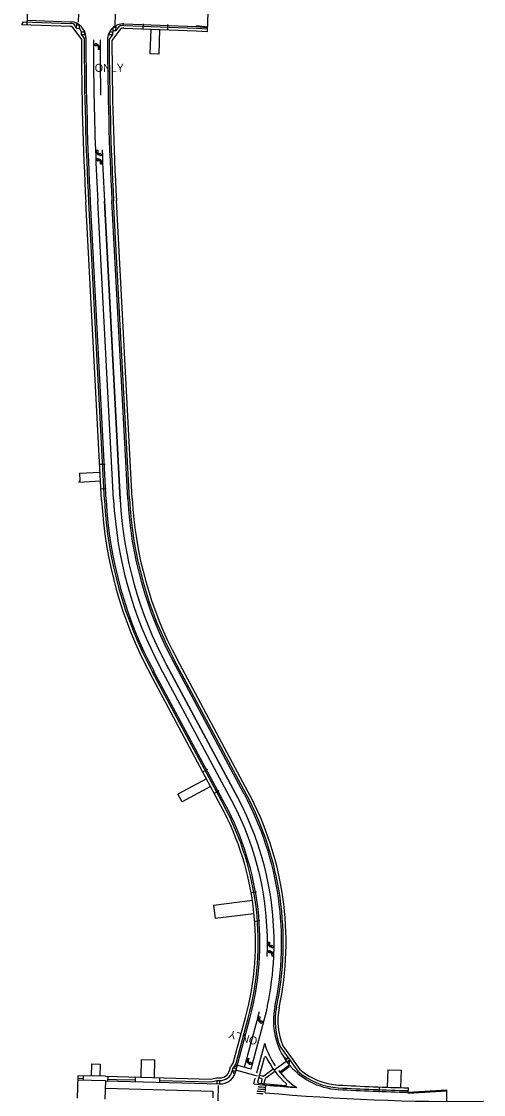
# Model space of a CAD drawing. Extents: x 979036 to 996074, y 1836928 to 1845163.
# Drawn here: x 992337 to 993169, y 1840671 to 1842602 of the extents above; entities that cross this region are included whole.
import ezdxf

# ---------------------------------------------------------------- set-up
doc = ezdxf.new("R2010")
doc.units = 0
for name, color, linetype in [('R_Proposed Road', 7, 'Continuous'), ('STRIPE_White Crosswalk', 7, 'Continuous'), ('STRIPE_White Stopbar', 7, 'Continuous'), ('STRIPE_White Turn Arrow', 7, 'Continuous'), ('STRIPE_White_6in', 7, 'Continuous'), ('STRIPE_White_ONLY', 7, 'Continuous'), ('STRIPE_White_Yield Tri', 7, 'Continuous'), ('STRIPE_Yellow Dbl 6in', 7, 'Continuous'), ('STRIPE_Yellow_10_30 SKIP', 7, 'Continuous'), ('STRIPE_Yellow_45_Diag_8in', 7, 'Continuous')]:
    doc.layers.add(name, color=color, linetype=linetype)

msp = doc.modelspace()

# ---------------------------------------------------------------- linework, layer by layer
at = {"layer": 'R_Proposed Road'}
for p, q in [((992348.7, 1842643.5), (992347, 1842596.5)), ((992671.8, 1842584.2), (992673.6, 1842635.6)), ((992340.2, 1842601.8), (992337.3, 1842596.9)), ((992337.3, 1842596.9), (992425.4, 1842593.7)), ((992340.2, 1842601.8), (992425.6, 1842598.7)), ((992347.3, 1842604.5), (992425.7, 1842601.7)), ((992427.9, 1842593.4), (992445.2, 1842569.9)), ((992430.8, 1842597.9), (992436.5, 1842590.2)), ((992436.5, 1842590.2), (992436.8, 1842599)), ((992436.5, 1842590.2), (992441.5, 1842590)), ((992436.7, 1842596.2), (992441.7, 1842596)), ((992441.5, 1842590), (992441.7, 1842596)), ((992441.5, 1842590), (992445.4, 1842583.1)), ((992502.1, 1842585.5), (992502.3, 1842591.5)), ((992507.3, 1842591.3), (992502.3, 1842591.5)), ((992507.1, 1842585.3), (992507.4, 1842594.9)), ((992507.1, 1842585.3), (992514, 1842594.3)), ((992521.4, 1842590.2), (992651.8, 1842585.4)), ((992521.6, 1842595.2), (992652, 1842590.4)), ((992521.7, 1842598.1), (992652.1, 1842593.4)), ((992556.2, 1842598.4), (992555.8, 1842588.9)), ((992600.2, 1842596.8), (992599.8, 1842587.3)), ((992652, 1842590.4), (992671.9, 1842589.2)), ((992652.1, 1842594.9), (992672.1, 1842593)), ((992652.1, 1842593.4), (992672, 1842591.5)), ((992445.4, 1842578.1), (992445.4, 1842583.1)), ((992451.4, 1842583.1), (992445.4, 1842583.1)), ((992445.4, 1842578.1), (992450.2, 1842571.6)), ((992452.7, 1842578.1), (992445.4, 1842578.1)), ((992451.4, 1842578.1), (992451.4, 1842583.1)), ((992501.5, 1842578.1), (992493.4, 1842578.1)), ((992495.2, 1842569.8), (992501.5, 1842578.1)), ((992501.5, 1842583.1), (992495.5, 1842583.1)), ((992495.5, 1842578.1), (992495.5, 1842583.1)), ((992500.2, 1842568.1), (992516.9, 1842589.8)), ((992502.1, 1842585.5), (992501.5, 1842583.1)), ((992501.5, 1842578.1), (992501.5, 1842583.1)), ((992507.1, 1842585.3), (992502.1, 1842585.5)), ((992569.8, 1842588.4), (992568.2, 1842544.1)), ((992585.8, 1842587.8), (992584.2, 1842543.6)), ((992651.8, 1842585.4), (992671.8, 1842584.2)), ((992584.2, 1842543.6), (992568.2, 1842544.1)), ((992481.5, 1841740.8), (992453.2, 1842277.1)), ((992486.5, 1841741), (992458.2, 1842277.4)), ((992489.5, 1841741.2), (992461.2, 1842277.5)), ((992528.4, 1841743.3), (992500.1, 1842279.6)), ((992531.4, 1841743.4), (992503.1, 1842279.7)), ((992536.4, 1841743.7), (992508.1, 1842280)), ((992478.1, 1841805.4), (992487.6, 1841805.9)), ((992441.4, 1841789.5), (992478.8, 1841791.5)), ((992440.6, 1841773.4), (992479.7, 1841775.5)), ((992480.4, 1841761.5), (992489.9, 1841762)), ((992738.3, 1841211.7), (992610.1, 1841450.8)), ((992740.9, 1841213.2), (992612.8, 1841452.3)), ((992745.3, 1841215.5), (992617.2, 1841454.6)), ((992703.9, 1841193.3), (992575.7, 1841432.4)), ((992696.9, 1841189.5), (992568.7, 1841428.6)), ((992701.3, 1841191.9), (992573.1, 1841431)), ((992670.1, 1841239.5), (992618.7, 1841212)), ((992671.8, 1841256.3), (992663.5, 1841251.8)), ((992677.6, 1841225.4), (992626.3, 1841197.9)), ((992626.3, 1841197.9), (992618.7, 1841212)), ((992692.6, 1841217.5), (992684.3, 1841213)), ((992760, 1841035.2), (992750.6, 1841034.1)), ((992752.8, 1841020.3), (992682.9, 1841011.6)), ((992682.9, 1841011.6), (992685.9, 1840987.8)), ((992755.7, 1840996.4), (992685.9, 1840987.8)), ((992766.4, 1840983.6), (992757, 1840982.5)), ((992718.9, 1840729.8), (992740.5, 1840810)), ((992722.3, 1840711.4), (992748.3, 1840808)), ((992723.6, 1840727.8), (992745.4, 1840808.7)), ((992803.3, 1840756.4), (992834.7, 1840712.9)), ((992807.7, 1840758.9), (992838.4, 1840716.3)), ((992762.6, 1840693.9), (992774.4, 1840737.7)), ((992809.5, 1840738), (992817.5, 1840736.7)), ((992817.5, 1840736.7), (992812.7, 1840733.2)), ((992821.6, 1840739.7), (992824.5, 1840735.6)), ((992463.1, 1840726.5), (992462.5, 1840704.3)), ((992463.1, 1840726.5), (992479.1, 1840725.9)), ((992479.1, 1840725.9), (992478.5, 1840704.1)), ((992552.5, 1840702.2), (992553.4, 1840734.3)), ((992553.4, 1840734.3), (992577.4, 1840733.6)), ((992576.5, 1840701.5), (992577.4, 1840733.6)), ((992711.6, 1840714.2), (992713.4, 1840720.9)), ((992718.9, 1840729.8), (992713.4, 1840720.9)), ((992716.5, 1840712.9), (992718.1, 1840718.9)), ((992723.6, 1840727.8), (992718.1, 1840718.9)), ((992725.4, 1840723.1), (992718.1, 1840718.9)), ((992723.9, 1840717.3), (992718.1, 1840718.9)), ((992773.3, 1840704.8), (992790.4, 1840717.1)), ((992820.4, 1840732.7), (992815.6, 1840729.2)), ((992819.2, 1840724.6), (992820.4, 1840732.7)), ((992438.5, 1840704.8), (992437.4, 1840664.3)), ((992448.4, 1840699.6), (992438.4, 1840699.8)), ((992488.5, 1840703.9), (992438.5, 1840704.8)), ((992448.5, 1840704.6), (992448.3, 1840696.6)), ((992488.5, 1840703.9), (992678.2, 1840698.7)), ((992492.5, 1840703.8), (992492.3, 1840695.8)), ((992492.4, 1840698.7), (992508.4, 1840698.4)), ((992508.4, 1840698.4), (992542.4, 1840697.4)), ((992542.3, 1840693.1), (992542.5, 1840702.4)), ((992586.2, 1840691.9), (992586.5, 1840701.2)), ((992678.2, 1840698.7), (992688.3, 1840701.4)), ((992688.3, 1840701.4), (992694.3, 1840701.3)), ((992722.6, 1840712.5), (992716.8, 1840714.1)), ((992720.8, 1840707.2), (992716.8, 1840714.1)), ((992768.9, 1840700), (992764.6, 1840701.2)), ((992765.9, 1840706), (992771.6, 1840704.5)), ((992768.6, 1840691), (992770.3, 1840697.6)), ((992773.6, 1840690.6), (992776.2, 1840700.1)), ((992776.9, 1840701.2), (992793.3, 1840713)), ((992996.5, 1840715.8), (992995.6, 1840684.3)), ((992996.5, 1840715.8), (993020.5, 1840715.1)), ((993020.5, 1840715.1), (993019.6, 1840683.5)), ((992488.3, 1840695.9), (992438.3, 1840696.8)), ((992488.3, 1840695.9), (992487.4, 1840662.9)), ((992488.3, 1840695.9), (992694, 1840690.3)), ((992586.4, 1840696.2), (992678.8, 1840693.7)), ((992678.8, 1840693.7), (992688.9, 1840696.4)), ((992688.9, 1840696.4), (992694.1, 1840696.3)), ((992764.4, 1840691.4), (992785.5, 1840689.5)), ((992981.2, 1840675.2), (992981.6, 1840684.7)), ((993033.1, 1840675.2), (993102.9, 1840679.3)), ((993033.3, 1840673.7), (993033.6, 1840683.2)), ((993102.7, 1840635.2), (993102.9, 1840679.3)), ((993033.2, 1840673.7), (993102.9, 1840677.8))]:
    msp.add_line(p, q, dxfattribs=at)
for points in [[(992441.4, 1841789.5), (992442, 1841776.5), (992440.6, 1841773.4)], [(992688.9, 1840696.4), (992688.7, 1840690.4)], [(992693.9, 1840696.3), (992693.7, 1840690.3)]]:
    msp.add_lwpolyline(points, dxfattribs=at)
for centre, radius, start, end in [((992424.7, 1842573.2), 20.5, 80.8565, 87.9024), ((992424.7, 1842573.2), 25.5, 76.0433, 87.9024), ((992424.7, 1842573.2), 28.5, 0.0744, 87.9024), ((992520.7, 1842569.7), 28.5, 87.9024, 180.1112), ((992520.7, 1842569.7), 25.5, 87.9024, 105.1165), ((992520.7, 1842569.7), 20.5, 87.9024, 100.6335), ((998202.2, 1842580.7), 5752.1, 180.09065, 183.02281), ((998202.2, 1842580.7), 5749.1, 180.07443, 183.02281), ((998202.2, 1842580.7), 5757.1, 180.10692, 183.02281), ((998202.2, 1842580.7), 5710.1, 180.1112, 183.0228), ((992520.7, 1842569.7), 25.5, 179.6047, 180.1112), ((998202.2, 1842580.7), 5707.1, 180.1112, 183.0228), ((998202.2, 1842580.7), 5707.1, 180.1112, 183.0228), ((998202.2, 1842580.7), 5702.1, 180.1261, 183.0228), ((998202.2, 1842580.7), 5702.1, 180.1261, 183.0228), ((993224.2, 1841780), 743.7, 183.0228, 208.1934), ((993224.2, 1841780), 738.7, 183.0228, 208.1934), ((993224.2, 1841780), 735.7, 183.0228, 208.1934), ((993224.2, 1841780), 696.7, 183.0228, 208.1934), ((993224.2, 1841780), 693.7, 183.0228, 208.1934), ((993224.2, 1841780), 688.7, 183.0228, 208.1934), ((992240.2, 1840944.7), 565.2, 348.1671, 28.1934), ((992240.2, 1840944.7), 568.2, 348.1671, 28.1934), ((992240.2, 1840944.7), 573.2, 348.1671, 28.1934), ((992240.2, 1840944.7), 518.2, 344.9354, 28.1934), ((992240.2, 1840944.7), 523.2, 344.9354, 28.1934), ((992240.2, 1840944.7), 526.2, 344.9354, 28.1934), ((992914.2, 1840803.5), 123.5, 168.1671, 266.7749), ((992914.2, 1840803.5), 120.5, 168.1671, 202.9851), ((992914.2, 1840803.5), 115.5, 168.1671, 202.7083), ((992776.3, 1840737.2), 2, 25.6869, 164.9354), ((992914.2, 1840803.5), 151, 205.6869, 228.317), ((992694.7, 1840718.8), 28.5, 268.4354, 344.9354), ((992694.7, 1840718.8), 22.5, 268.4354, 344.9354), ((992694.7, 1840718.8), 17.5, 268.4354, 344.9354), ((992768.4, 1840698.1), 2, 344.9354, 74.9354), ((992772.2, 1840706.4), 2, 254.9354, 305.851), ((992778.1, 1840699.6), 2, 125.851, 164.9354), ((992914.2, 1840803.5), 120.5, 228.717, 266.7749), ((992914.2, 1840803.5), 115.5, 228.9937, 266.7749), ((992764.5, 1840693.4), 2, 164.9354, 264.9354), ((993121.3, 1844478.4), 3803.7, 264.9354, 265.3407), ((992812.5, 1840689.2), 2, 265.3407, 48.317), ((993121.3, 1844478.4), 3804.2, 266.7749, 268.6736), ((993121.3, 1844478.4), 3801.2, 266.7749, 268.676), ((993121.3, 1844478.4), 3796.2, 266.7749, 268.676)]:
    msp.add_arc(centre, radius, start, end, dxfattribs=at)
at = {"layer": 'STRIPE_White Crosswalk'}
for p, q in [((992440.5, 1842632.3), (992439.4, 1842601.3)), ((992506.3, 1842632.1), (992505, 1842596.3)), ((992813, 1840730.1), (992791.8, 1840715)), ((992762.3, 1840704.4), (992724.7, 1840714.5)), ((992691.2, 1840687.3), (992690.4, 1840659.5))]:
    msp.add_line(p, q, dxfattribs=at)
for points in [[(992773.4, 1840680.7), (992773.3, 1840679.7), (992763.3, 1840680.6), (992763.4, 1840681.6)], [(992774.4, 1840684.5), (992774.3, 1840683.6), (992764.4, 1840684.4), (992764.5, 1840685.4)], [(992775.5, 1840688.4), (992775.4, 1840687.4), (992765.4, 1840688.3), (992765.5, 1840689.3)], [(992771.3, 1840673), (992771.2, 1840672), (992761.2, 1840672.8), (992761.3, 1840673.8)], [(992772.3, 1840676.8), (992772.2, 1840675.8), (992762.3, 1840676.7), (992762.4, 1840677.7)]]:
    msp.add_lwpolyline(points, close=True, dxfattribs=at)
at = {"layer": 'STRIPE_White Stopbar'}
for p, q in [((992750.2, 1840717), (992727, 1840723.2)), ((992776, 1840674.3), (992777.2, 1840688.2)), ((992681.9, 1840677.1), (992681.5, 1840665.1))]:
    msp.add_line(p, q, dxfattribs=at)
at = {"layer": 'STRIPE_White Turn Arrow'}
for points in [[(992471.9, 1842558), (992468.3, 1842560.3), (992471.4, 1842563.3), (992471.6, 1842561.6), (992472.3, 1842561.6), (992472.8, 1842561.6), (992473.6, 1842561.4), (992474.6, 1842561), (992475.3, 1842560.6), (992475.9, 1842560.1), (992476.6, 1842559.4), (992477, 1842558.8), (992477.4, 1842558), (992477.7, 1842557.1), (992477.8, 1842556.1), (992477.8, 1842552.2), (992475.8, 1842552.2), (992475.8, 1842555.8), (992475.8, 1842556.5), (992475.5, 1842557.2), (992475.2, 1842558), (992474.6, 1842558.7), (992474.3, 1842558.9), (992473.7, 1842559.3), (992472.9, 1842559.5), (992472.2, 1842559.6), (992471.8, 1842559.6)], [(992478.5, 1842365.3), (992482.3, 1842363.1), (992479.3, 1842360), (992479, 1842361.7), (992478.4, 1842361.6), (992477.8, 1842361.6), (992477, 1842361.8), (992476, 1842362.1), (992475.3, 1842362.5), (992474.6, 1842363), (992473.9, 1842363.6), (992473.5, 1842364.3), (992473, 1842365), (992472.7, 1842365.9), (992472.5, 1842366.9), (992472.4, 1842370.8), (992474.4, 1842370.9), (992474.6, 1842367.3), (992474.6, 1842366.6), (992474.9, 1842365.9), (992475.3, 1842365.1), (992475.9, 1842364.5), (992476.2, 1842364.3), (992476.8, 1842363.9), (992477.6, 1842363.7), (992478.3, 1842363.6), (992478.7, 1842363.6)], [(992475.4, 1842350.9), (992471.5, 1842353), (992474.6, 1842356.2), (992474.8, 1842354.5), (992475.5, 1842354.6), (992476.1, 1842354.6), (992476.9, 1842354.4), (992477.8, 1842354.1), (992478.6, 1842353.7), (992479.2, 1842353.2), (992479.9, 1842352.6), (992480.4, 1842352), (992480.8, 1842351.2), (992481.1, 1842350.3), (992481.3, 1842349.3), (992481.5, 1842345.4), (992479.5, 1842345.4), (992479.3, 1842349), (992479.2, 1842349.6), (992479, 1842350.4), (992478.6, 1842351.1), (992478, 1842351.7), (992477.7, 1842351.9), (992477, 1842352.3), (992476.2, 1842352.5), (992475.5, 1842352.6), (992475.1, 1842352.6)], [(992784.2, 1840925.6), (992780.4, 1840927.8), (992783.5, 1840930.9), (992783.7, 1840929.3), (992784.4, 1840929.3), (992784.9, 1840929.3), (992785.7, 1840929.1), (992786.7, 1840928.8), (992787.4, 1840928.4), (992788.1, 1840927.9), (992788.8, 1840927.2), (992789.2, 1840926.6), (992789.6, 1840925.8), (992789.9, 1840924.9), (992790.1, 1840923.9), (992790.2, 1840920), (992788.2, 1840920), (992788.1, 1840923.6), (992788, 1840924.3), (992787.8, 1840925), (992787.4, 1840925.8), (992786.8, 1840926.4), (992786.5, 1840926.6), (992785.8, 1840927), (992785.1, 1840927.2), (992784.3, 1840927.3), (992783.9, 1840927.3)], [(992787.5, 1840940), (992791.3, 1840937.8), (992788.2, 1840934.7), (992788, 1840936.3), (992787.3, 1840936.3), (992786.8, 1840936.3), (992786, 1840936.5), (992785, 1840936.8), (992784.3, 1840937.2), (992783.6, 1840937.7), (992782.9, 1840938.3), (992782.5, 1840939), (992782.1, 1840939.7), (992781.8, 1840940.6), (992781.6, 1840941.6), (992781.5, 1840945.5), (992783.5, 1840945.6), (992783.6, 1840942), (992783.7, 1840941.3), (992783.9, 1840940.6), (992784.3, 1840939.8), (992784.9, 1840939.2), (992785.2, 1840939), (992785.9, 1840938.6), (992786.6, 1840938.4), (992787.4, 1840938.3), (992787.8, 1840938.3)], [(992769, 1840804.4), (992772, 1840801.3), (992768.2, 1840799.1), (992768.4, 1840800.8), (992767.8, 1840801), (992767.2, 1840801.1), (992766.5, 1840801.5), (992765.7, 1840802.1), (992765, 1840802.7), (992764.6, 1840803.3), (992764.1, 1840804.1), (992763.9, 1840804.9), (992763.6, 1840805.7), (992763.6, 1840806.7), (992763.7, 1840807.7), (992764.7, 1840811.4), (992766.6, 1840810.9), (992765.7, 1840807.4), (992765.6, 1840806.8), (992765.7, 1840806), (992765.8, 1840805.1), (992766.2, 1840804.4), (992766.5, 1840804.1), (992767, 1840803.6), (992767.7, 1840803.2), (992768.3, 1840802.9), (992768.7, 1840802.8)], [(992748.7, 1840729.7), (992751.7, 1840726.6), (992747.9, 1840724.5), (992748.1, 1840726.1), (992747.5, 1840726.3), (992746.9, 1840726.4), (992746.2, 1840726.8), (992745.4, 1840727.4), (992744.8, 1840728), (992744.3, 1840728.6), (992743.8, 1840729.4), (992743.6, 1840730.2), (992743.3, 1840731), (992743.3, 1840732), (992743.4, 1840733), (992744.4, 1840736.7), (992746.4, 1840736.2), (992745.5, 1840732.8), (992745.3, 1840732.1), (992745.4, 1840731.3), (992745.5, 1840730.5), (992745.9, 1840729.7), (992746.2, 1840729.4), (992746.7, 1840728.9), (992747.4, 1840728.5), (992748, 1840728.2), (992748.4, 1840728.1)]]:
    msp.add_lwpolyline(points, close=True, dxfattribs=at)
at = {"layer": 'STRIPE_White_6in'}
for p, q in [((992738.6, 1840720.1), (992761.3, 1840804.5)), ((992760.7, 1840710), (992775, 1840763)), ((992755.4, 1840690.2), (992758.1, 1840700.4)), ((992755.4, 1840690.2), (992765.5, 1840689.3)), ((992775.5, 1840688.4), (992785.3, 1840687.5)), ((992832.6, 1840683.6), (992785.3, 1840687.5))]:
    msp.add_line(p, q, dxfattribs=at)
for centre, radius, start, end in [((998202.2, 1842580.7), 5723.6, 180.1112, 181.1122), ((992240.2, 1840944.7), 539.7, 344.9354, 346.6912), ((992914.2, 1840803.5), 145, 196.2291, 213.9086), ((992914.2, 1840803.5), 145, 217.8589, 235.7574), ((993121.3, 1844478.4), 3805.7, 264.9354, 265.6499)]:
    msp.add_arc(centre, radius, start, end, dxfattribs=at)
at = {"layer": 'STRIPE_White_Yield Tri'}
for p, q in [((992811.1, 1840717.9), (992809.5, 1840716.7)), ((992809.5, 1840716.7), (992812, 1840714.8)), ((992812, 1840714.8), (992811.1, 1840717.9)), ((992813.5, 1840719.6), (992811.9, 1840718.5)), ((992811.9, 1840718.5), (992814.4, 1840716.6)), ((992814.4, 1840716.6), (992813.5, 1840719.6)), ((992815.9, 1840721.4), (992814.3, 1840720.2)), ((992814.3, 1840720.2), (992816.8, 1840718.3)), ((992816.8, 1840718.3), (992815.9, 1840721.4)), ((992818.4, 1840723.2), (992816.8, 1840722)), ((992816.8, 1840722), (992819.3, 1840720.1)), ((992819.3, 1840720.1), (992818.4, 1840723.2)), ((992803.8, 1840712.6), (992802.2, 1840711.4)), ((992802.2, 1840711.4), (992804.7, 1840709.6)), ((992804.7, 1840709.6), (992803.8, 1840712.6)), ((992806.2, 1840714.4), (992804.6, 1840713.2)), ((992804.6, 1840713.2), (992807.1, 1840711.3)), ((992807.1, 1840711.3), (992806.2, 1840714.4)), ((992808.7, 1840716.1), (992807, 1840715)), ((992807, 1840715), (992809.5, 1840713.1)), ((992809.5, 1840713.1), (992808.7, 1840716.1))]:
    msp.add_line(p, q, dxfattribs=at)
at = {"layer": 'STRIPE_Yellow Dbl 6in'}
for p, q in [((992778.5, 1840822.1), (992750.2, 1840717)), ((992487.9, 1840682.4), (992681.9, 1840677.1))]:
    msp.add_line(p, q, dxfattribs=at)
for centre, radius, start, end in [((998202.2, 1842580.7), 5735.6, 180.11115, 182.09371), ((992240.2, 1840944.7), 551.7, 348.1671, 357.3079), ((992517.4, 1840872.2), 265.9, 349.141, 351.2112), ((993121.3, 1844478.4), 3819.7, 264.8133, 270.7131)]:
    msp.add_arc(centre, radius, start, end, dxfattribs=at)
at = {"layer": 'STRIPE_Yellow_10_30 SKIP'}
for p, q in [((992503, 1841741.9), (992474.6, 1842278.2)), ((992503, 1841741.9), (992474.6, 1842278.2)), ((992514.9, 1841742.5), (992486.6, 1842278.9)), ((992486.6, 1842278.9), (992514.9, 1841742.5)), ((992715.8, 1841199.7), (992587.6, 1841438.8)), ((992715.8, 1841199.7), (992587.6, 1841438.8)), ((992726.4, 1841205.4), (992598.2, 1841444.5)), ((992598.2, 1841444.5), (992726.4, 1841205.4))]:
    msp.add_line(p, q, dxfattribs=at)
for centre, radius, start, end in [((998202.2, 1842580.7), 5735.6, 182.09371, 183.02281), ((998202.2, 1842580.7), 5735.6, 182.09371, 183.02281), ((998202.2, 1842580.7), 5723.6, 182.0937, 182.1132), ((998202.2, 1842580.7), 5723.6, 182.0937, 183.0228), ((998202.2, 1842580.7), 5723.6, 182.0937, 183.0228), ((993224.2, 1841780), 722.2, 183.0228, 208.1934), ((993224.2, 1841780), 722.2, 183.0228, 208.1934), ((993224.2, 1841780), 710.2, 183.0228, 208.1934), ((993224.2, 1841780), 710.2, 183.0228, 208.1934), ((992240.2, 1840944.7), 539.7, 357.3079, 28.1934), ((992240.2, 1840944.7), 539.7, 357.3079, 28.1934), ((992240.2, 1840944.7), 551.7, 357.3079, 28.1934), ((992240.2, 1840944.7), 551.7, 357.3079, 28.1934)]:
    msp.add_arc(centre, radius, start, end, dxfattribs=at)
at = {"layer": 'STRIPE_Yellow_45_Diag_8in'}
msp.add_line((992786.9, 1840873.7), (992786.5, 1840873.4), dxfattribs=at)

# ---------------------------------------------------------------- texts
at = {"layer": 'STRIPE_White_ONLY'}
for rotation, p in [(0.6555, (992469.2, 1842511.5)), (164.9354, (992763.2, 1840773.6))]:
    msp.add_text('ONLY', height=14.4, rotation=rotation, dxfattribs=at).set_placement(p)

doc.saveas('drawing.dxf')
